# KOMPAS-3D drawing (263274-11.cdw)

Referenced files in I:\контрольыне\: колесоcdw.cdw
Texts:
  Колесо
  Loner-XP
  WolfishLair
  Текст на чертеже
  Размерные надписи
  Шероховатость
  Линия-выноска #1
  Линия-выноска #2
  Линия-выноска #3
  Отклонения формы и база
  Заголовок таблицы
  Ячейка таблицы
  Стрелка вида
  Обозначение изменения
  Фигурная скобка
  Номер узла
  Марка координационной оси
  VRCB
  Выносная надпись
  Обозначение узла
  Марка/позиционное обозначение с линией-выноской
  Марка/позиционное обозначение на линии
  Марка/позиционное обозначение без линии-выноски
  Лит-Масса-Масштаб
  Материал-Предприятие
  Title Specification
  Body Specification ( left align )
  Body Specificaton ( centered )
  Ra 1.25
  Ra 3.2
  Ra 1.6
  . 192....240 HB
  2. Радиусы скруглений 9мм max
  3. Штамповочные уклоны  =7 .
  4.Неуказанные пред. отклонения размеров: отверстий +t2,
  валов -t2, остальных +/- t2/2 по ГОСТ 25670-83
  Модуль
  Число зубьев
  Угол наклона
  Направление линии зуба
  Нормальный исходный
  контур
  Коэффициент смещения
  Степень точности
  Делительный диаметр
  Обозначение чертежа
  сопряженного колеса
  Symbol type A
  шеврон
  ГОСТ
  Овчаренко В.В.
  Сталь 45 ГОСТ 543 - 71
  ВНУ им. Даля
  гр. МЗ - 06 в
Dimensions and other numbers on the sheet: 701.48.00.003; 7; 183,8; 0,7; 2 фаски; 1,5; 0,016; 0,025; 20; 50; 46; 78; 158; 0.016; 10; 35,2; 0.02; 0.06; 2; 81; 13755-81; -0,3; 178,75; 8-В; 701.48.00.002; 4; 1:1; 1; 701.13.00.003-; 0; 3; 5; 6; 8; 9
